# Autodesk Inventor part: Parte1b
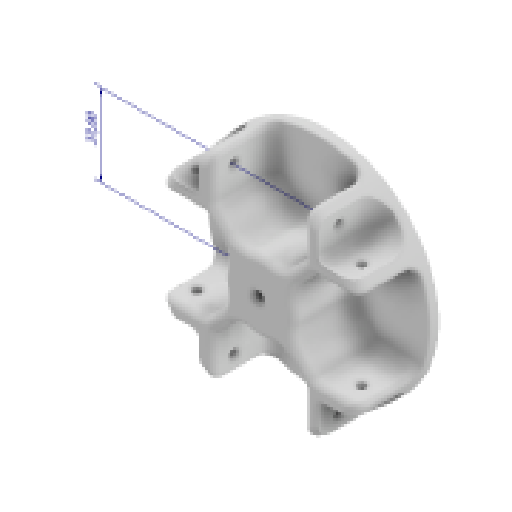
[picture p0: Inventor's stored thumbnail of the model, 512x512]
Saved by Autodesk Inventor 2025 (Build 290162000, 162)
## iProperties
Created: 2025-05
Part Number: Parte1b
Material: Generico
Document SubType Name: Modeling
Designer: R5800u
Density: 1 g/cm^3
Appearance: Default
Author: R5800u
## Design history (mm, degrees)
node "Annotazioni"
  node "Quota lineare 1" dims "d0" = 100, "d1" = 45 deg, "d3" = 25, "d8" = 6, "d9" = 6, "d10" = 3, "d11" = 3, "d22" = 6, "d23" = 6, "d45" = 37 (derived)
sketch "Schizzo1" dims "d0" = 100
  geometry: L1 (0, 0)-(35.355, 35.355); L2 (0, 0)-(50, 0); L3 (20.572, 20.572)-(20.572, 45.572); L4 (20.572, 20.572)-(45.572, 20.572); L5 (0, 0)-(0, 44.829) reference; L6 (-20.572, 20.572)-(-20.572, 45.572); L7 (0, 0)-(-35.355, 35.355); L8 (-20.572, 20.572)-(-45.572, 20.572); L9 (0, 0)-(56.569, 0); L10 (26.572, 42.355)-(26.572, 26.572); L11 (26.572, 26.572)-(42.355, 26.572); L12 (-26.572, 42.355)-(-26.572, 26.572); L13 (-26.572, 26.572)-(-42.355, 26.572); L14 (-20.572, 24.815)-(0, 4.243); L15 (0, 4.243)-(20.572, 24.815); L16 (24.815, 20.572)-(0, -4.243); L17 (0, -4.243)-(-24.815, 20.572); L18 (20.572, -20.572)-(20.572, -45.572); L19 (0, -4.243)-(20.572, -24.815); L20 (26.572, -42.355)-(26.572, -26.572); L21 (24.815, -20.572)-(0, 4.243); L22 (0, 0)-(35.355, -35.355); L23 (26.572, -26.572)-(42.355, -26.572); L24 (20.572, -20.572)-(45.572, -20.572); L25 (0, 0)-(0, -44.829); L26 (-20.572, -24.815)-(0, -4.243); L27 (0, 4.243)-(-24.815, -20.572); L28 (0, 0)-(-35.355, -35.355); L29 (-20.572, -20.572)-(-20.572, -45.572); L30 (-26.572, -42.355)-(-26.572, -26.572); L31 (-26.572, -26.572)-(-42.355, -26.572); L32 (-20.572, -20.572)-(-45.572, -20.572); 3 further points
  constraints: 64 end point, 25 symmetric about line, 13 point on line, 3 vertical, 2 coincident, 2 horizontal, 1 equal length, 9 other
  dimensions: "d1" = 45 deg angle of L2 L1; "d3" = 25 distance of L3.start L4.end; "d8" = 6 distance between parallel lines of L3 L10; "d9" = 6 distance between parallel lines of L6 L12; "d10" = 3 distance between parallel lines of L7 L14; "d11" = 3 distance between parallel lines of L1 L16; "d22" = 6 distance between parallel lines of L4 L11; "d23" = 6 distance between parallel lines of L8 L13
extrude "Estrusione1" new body sketch "Schizzo1" stored distance "d4" = 75; taper "d5" = 0 deg
node "Piano di lavoro1"
sketch "Schizzo3" dims "d24" = 100
  geometry: L1 (0, 0)-(35.355, 35.355); L2 (0, 0)-(50, 0); L3 (20.572, 20.572)-(20.572, 45.572); L4 (20.572, 20.572)-(45.572, 20.572); L5 (0, 0)-(0, 44.829); L6 (-20.572, 20.572)-(-20.572, 45.572); L7 (0, 0)-(-35.355, 35.355); L8 (-20.572, 20.572)-(-45.572, 20.572); L9 (0, 0)-(56.569, 0); L10 (26.572, 42.355)-(26.572, 26.572); L11 (26.572, 26.572)-(42.355, 26.572); L12 (-26.572, 42.355)-(-26.572, 26.572); L13 (-26.572, 26.572)-(-42.355, 26.572); L14 (-20.572, 24.815)-(0, 4.243); L15 (0, 4.243)-(20.572, 24.815); L16 (24.815, 20.572)-(0, -4.243); L17 (0, -4.243)-(-24.815, 20.572); L18 (20.572, -20.572)-(20.572, -45.572); L19 (0, -4.243)-(20.572, -24.815); L20 (26.572, -42.355)-(26.572, -26.572); L21 (24.815, -20.572)-(0, 4.243); L22 (0, 0)-(35.355, -35.355); L23 (26.572, -26.572)-(42.355, -26.572); L24 (20.572, -20.572)-(45.572, -20.572); L25 (0, 0)-(0, -44.829); L26 (-20.572, -24.815)-(0, -4.243); L27 (0, 4.243)-(-24.815, -20.572); L28 (0, 0)-(-35.355, -35.355); L29 (-20.572, -20.572)-(-20.572, -45.572); L30 (-26.572, -42.355)-(-26.572, -26.572); L31 (-26.572, -26.572)-(-42.355, -26.572); L32 (-20.572, -20.572)-(-45.572, -20.572); 16 further points
  constraints: 64 end point, 25 symmetric about line, 13 point on line, 2 coincident, 2 horizontal, 2 parallel, 2 vertical, 1 equal length, 9 other
  dimensions: "d25" = 45 deg angle of L2 L1; "d26" = 25 distance of L3.start L4.end; "d27" = 6 distance between parallel lines of L3 L10; "d28" = 6 distance between parallel lines of L6 L12; "d29" = 3 distance between parallel lines of L7 L14; "d30" = 3 distance between parallel lines of L1 L16; "d31" = 6 distance between parallel lines of L4 L11; "d32" = 6 distance between parallel lines of L8 L13; "d41" = 3 distance between parallel lines of L1 L15; "d42" = 3 distance between parallel lines of L7 L17; "d63" = 25 distance of L18.start L24.end (derived); "d64" = 25 distance of L18.start L18.end (derived); "d65" = 41.14378 distance between parallel lines of L32 L8 (derived); "d66" = 41.14378 distance between parallel lines of L24 L4 (derived); "d67" = 41.14378 distance between parallel lines of L3 L6 (derived); "d68" = 41.14378 distance between parallel lines of L18 L29 (derived)
extrude "Estrusione4" cut sketch "Schizzo3" extent not by distance; stored distance "d33" = 30; taper "d34" = 0 deg
sketch "Schizzo4"
  geometry: L1 (45.572, 37.5)-(45.572, 3) reference; L2 (45.572, 20.25)-(0, 20.25); L3 (0, 3)-(0, 37.5) reference; C1 r 2 at (37, 20.25); 2 further points
  constraints: 2 end point, 2 midpoint, 1 centre point, 1 coincident, 1 point on line
  dimensions: "d36" = 37 horizontal distance of point (0, 0) point (37, 20.25); "d37" = 4 diameter of C1
extrude "Estrusione5" cut sketch "Schizzo4" extent not by distance; stored distance "d38" = 0; taper "d39" = 0 deg
pattern_circular "Serie circolare1" dims angle "d47" = 360 deg
fillet "Raccordo1" dims "d49" = 2
pattern_circular "Serie circolare2" dims angle "d51" = 360 deg
sketch "Schizzo5"
  geometry: C1 r 50 at (0, 0) reference; 1 further point
extrude "Estrusione6" cut sketch "Schizzo5" distance "d53" = 36; taper "d54" = 0 deg
sketch "Schizzo6"
  geometry: C1 r 16 at (0, 0); 1 further point
  constraints: 1 centre point, 1 coincident
  dimensions: "d55" = 32 diameter of C1
extrude "Estrusione7" join sketch "Schizzo6" stored distance "d56" = 36; taper "d57" = 0 deg
fillet "Raccordo2" dims "d58" = 10
fillet "Raccordo3" dims "d59" = 3
pattern_circular "Serie circolare3" dims angle "d61" = 360 deg
sketch "Schizzo7"
  geometry: C1 r 2.5 at (0, 0); 1 further point
  constraints: 1 centre point, 1 coincident
  dimensions: "d69" = 5 diameter of C1
extrude "Estrusione8" cut sketch "Schizzo7" extent not by distance; stored distance "d70" = 10; taper "d71" = 0 deg
sketch "Schizzo8"
  geometry: L1 (18.043, 13.8)-(23.936, 19.693) reference; L2 (26.057, 20.572)-(42.362, 20.572) reference; L3 (42.355, 26.572)-(26.572, 26.572) reference; L4 (26.572, 26.572)-(26.572, 42.355) reference; L5 (20.572, 42.362)-(20.572, 26.057) reference; L6 (19.693, 23.936)-(13.8, 18.043) reference; L7 (-13.8, 18.043)-(-19.693, 23.936) reference; L8 (-20.572, 26.057)-(-20.572, 42.362) reference; L9 (-26.572, 42.355)-(-26.572, 26.572) reference; L10 (-26.572, 26.572)-(-42.355, 26.572) reference; L11 (-42.362, 20.572)-(-26.057, 20.572) reference; L12 (-23.936, 19.693)-(-18.043, 13.8) reference; L13 (-18.043, -13.8)-(-23.936, -19.693) reference; L14 (-26.057, -20.572)-(-42.362, -20.572) reference; L15 (-42.355, -26.572)-(-26.572, -26.572) reference; L16 (-26.572, -26.572)-(-26.572, -42.355) reference; L17 (-20.572, -42.362)-(-20.572, -26.057) reference; L18 (-19.693, -23.936)-(-13.8, -18.043) reference; L19 (13.8, -18.043)-(19.693, -23.936) reference; L20 (20.572, -26.057)-(20.572, -42.362) reference; L21 (26.572, -42.355)-(26.572, -26.572) reference; L22 (26.572, -26.572)-(42.355, -26.572) reference; L23 (42.362, -20.572)-(26.057, -20.572) reference; L24 (23.936, -19.693)-(18.043, -13.8) reference; C1 r 2.5 at (0, 0) reference; A1 r 3 centre (26.057, 17.572) between (26.057, 20.572) and (23.936, 19.693) reference; A2 r 50 centre (0, 0) between (44.127, 23.512) and (42.355, 26.572) reference; A3 r 50 centre (0, 0) between (26.572, 42.355) and (23.512, 44.127) reference; A4 r 2 centre (22.572, 42.362) between (23.512, 44.127) and (20.572, 42.362) reference; A5 r 3 centre (17.572, 26.057) between (19.693, 23.936) and (20.572, 26.057) reference; A6 r 10 centre (6.729, 25.114) between (4.141, 15.455) and (13.8, 18.043) reference; A7 r 16 centre (0, 0) between (4.141, 15.455) and (-4.141, 15.455) reference; A8 r 10 centre (-6.729, 25.114) between (-13.8, 18.043) and (-4.141, 15.455) reference; A9 r 3 centre (-17.572, 26.057) between (-20.572, 26.057) and (-19.693, 23.936) reference; A10 r 2 centre (-22.572, 42.362) between (-20.572, 42.362) and (-23.512, 44.127) reference; A11 r 50 centre (0, 0) between (-23.512, 44.127) and (-26.572, 42.355) reference; A12 r 50 centre (0, 0) between (-42.355, 26.572) and (-44.127, 23.512) reference; A13 r 3 centre (-26.057, 17.572) between (-23.936, 19.693) and (-26.057, 20.572) reference; A14 r 10 centre (-25.114, 6.729) between (-15.455, 4.141) and (-18.043, 13.8) reference; A15 r 16 centre (0, 0) between (-15.455, 4.141) and (-15.455, -4.141) reference; A16 r 10 centre (-25.114, -6.729) between (-18.043, -13.8) and (-15.455, -4.141) reference; A17 r 3 centre (-26.057, -17.572) between (-26.057, -20.572) and (-23.936, -19.693) reference; A18 r 50 centre (0, 0) between (-44.127, -23.512) and (-42.355, -26.572) reference; A19 r 50 centre (0, 0) between (-26.572, -42.355) and (-23.512, -44.127) reference; A20 r 3 centre (-17.572, -26.057) between (-19.693, -23.936) and (-20.572, -26.057) reference; A21 r 10 centre (-6.729, -25.114) between (-4.141, -15.455) and (-13.8, -18.043) reference; A22 r 16 centre (0, 0) between (-4.141, -15.455) and (4.141, -15.455) reference; A23 r 10 centre (6.729, -25.114) between (13.8, -18.043) and (4.141, -15.455) reference; A24 r 3 centre (17.572, -26.057) between (20.572, -26.057) and (19.693, -23.936) reference; A25 r 50 centre (0, 0) between (23.512, -44.127) and (26.572, -42.355) reference; A26 r 50 centre (0, 0) between (42.355, -26.572) and (44.127, -23.512) reference; A27 r 3 centre (26.057, -17.572) between (23.936, -19.693) and (26.057, -20.572) reference; A28 r 10 centre (25.114, -6.729) between (15.455, -4.141) and (18.043, -13.8) reference; A29 r 16 centre (0, 0) between (15.455, -4.141) and (15.455, 4.141) reference; A30 r 10 centre (25.114, 6.729) between (18.043, 13.8) and (15.455, 4.141) reference; A31 r 2 centre (42.362, 22.572) between (42.362, 20.572) and (44.127, 23.512) reference; A32 r 2 centre (-42.362, 22.572) between (-44.127, 23.512) and (-42.362, 20.572) reference; A33 r 2 centre (-42.362, -22.572) between (-42.362, -20.572) and (-44.127, -23.512) reference; A34 r 2 centre (-22.572, -42.362) between (-23.512, -44.127) and (-20.572, -42.362) reference; A35 r 2 centre (22.572, -42.362) between (20.572, -42.362) and (23.512, -44.127) reference; A36 r 2 centre (42.362, -22.572) between (44.127, -23.512) and (42.362, -20.572) reference; 1 further point
extrude "Estrusione9" cut sketch "Schizzo8" distance "d72" = 8; taper "d73" = 0 deg
fillet "Raccordo5" dims "d75" = 5
fillet "Raccordo6" dims "d76" = 3
fillet "Raccordo7" dims "d77" = 3
fillet "Raccordo8" dims "d78" = 8.5
fillet "Raccordo9" dims "d79" = 5
fillet "Raccordo11" dims "d84" = 1
feature "ף耀ץ耀ק耀ש耀׫耀׭耀ׯ耀ױ耀" dims "d0" = 100, "d1" = 45 deg, "d3" = 25, "d4" = 75, "d5" = 0, "d8" = 6, "d9" = 6, "d10" = 3, "d11" = 3, "d12" = 3, "d18" = 2, "d19" = 2, "d22" = 6, "d23" = 6, "d24" = 100, "d25" = 45 deg, "d26" = 25, "d27" = 6, "d28" = 6, "d29" = 3, "d30" = 3, "d31" = 6, "d32" = 6, "d33" = 30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
feature "ٳ耀ٵ耀ٷ耀ٹ耀ٻ耀ٽ耀ٿ耀ځ耀" dims "d0" = 100, "d1" = 45 deg, "d3" = 25, "d4" = 75, "d5" = 0, "d8" = 6, "d9" = 6, "d10" = 3, "d11" = 3, "d12" = 3, "d18" = 2, "d19" = 2, "d22" = 6, "d23" = 6, "d24" = 100, "d25" = 45 deg, "d26" = 25, "d27" = 6, "d28" = 6, "d29" = 3, "d30" = 3, "d31" = 6, "d32" = 6, "d33" = 30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
node "Solido1"
node "Linea chiusa proiettata1"
